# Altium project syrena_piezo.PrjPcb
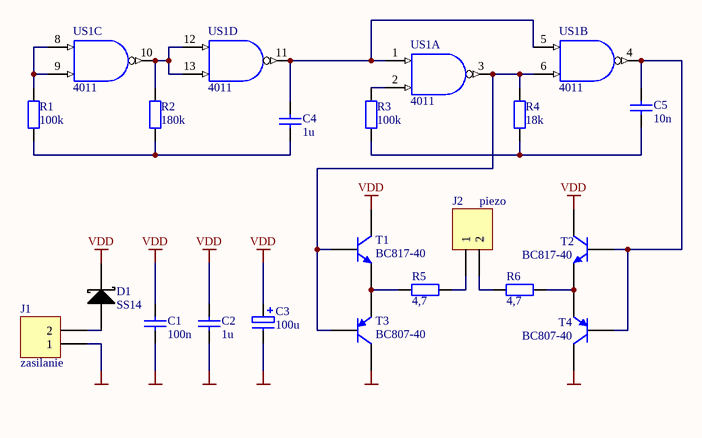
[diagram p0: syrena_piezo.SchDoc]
1 sheet, 19 parts. Net scope: global (net labels, ports and power ports of the same name join across sheets).
Board file: syrena_piezo.PcbDoc

## Sheet syrena_piezo.SchDoc
size A4

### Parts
C1  100n  [MELF-0805]
C2  1u  [MELF-0805]
C3  100u  [2,5/7mm le抗cy elektrolit]
C4  1u  [MELF-0805]
C5  10n  [MELF-0805]
D1  SS14  [SMA/DO-214AC]
J1  zasilanie  [HDR1X2]
J2  piezo  [HDR1X2]
R1  100k  [MELF-0805]
R2  180k  [MELF-0805]
R3  100k  [MELF-0805]
R4  18k  [MELF-0805]
R5  4,7  [MELF-1206]
R6  4,7  [MELF-1206]
T1  BC817-40  [318-08]
T2  BC817-40  [318-08]
T3  BC807-40  [318-08]
T4  BC807-40  [318-08]
US1  4011  [751A-03_N]  (parts A,B,C,D of 4)

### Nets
GND: C1.1 C2.1 C3.2 J1.1 T3.3(C) T4.3(C) US1.7(GND)
VDD: C1.2 C2.2 C3.1 D1.2(K) T1.3(C) T2.3(C) US1.14(VDD)
NetC4_1: C4.1 R1.1 R2.1
NetC4_2: C4.2 US1.1(A) US1.5(A) US1.11(~{Y})
NetC5_1: C5.1 R3.1 R4.1
NetC5_2: C5.2 T2.1(B) T4.1(B) US1.4(~{Y})
NetD1_1: D1.1(A) J1.2
NetJ2_1: J2.1 R5.2
NetJ2_2: J2.2 R6.1
NetR1_2: R1.2 US1.8(A) US1.9(B)
NetR2_2: R2.2 US1.10(~{Y}) US1.12(A) US1.13(B)
NetR3_2: R3.2 US1.2(B)
NetR4_2: R4.2 T1.1(B) T3.1(B) US1.3(~{Y}) US1.6(B)
NetR5_1: R5.1 T1.2(E) T3.2(E)
NetR6_2: R6.2 T2.2(E) T4.2(E)

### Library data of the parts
C1 C2 C4 C5 = kondensator
C3 = kond biegunowy: Polarized Capacitor
D1 = D Schottky: Schottky Diode
J1 J2 = Header 2: Header, 2-Pin
R1-R6 = rezystor
T1 T2 = BC846ALT1: General Purpose Transistor NPN Silicon
T3 T4 = BC857ALT1: General Purpose Transistor PNP Silicon
US1 = MC14011BD: Quad 2-Input NAND Gate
